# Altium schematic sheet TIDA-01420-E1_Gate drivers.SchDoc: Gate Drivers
size 431 x 279 mm; Date: Not shown in title block; ApprovedBy: Not shown in title block; CheckedBy: Not shown in title block; Author: Not shown in title block; CompanyName: Not shown in title block; DrawnBy: PN; Engineer: PN; Organization: Not shown in title block; Address1: Not shown in title block; Address2: Not shown in title block; Address3: Not shown in title block; Address4: Not shown in title block; DocumentNumber: 1; Revision: Use project parameter SCH_Rev; SheetNumber: 2; SheetTotal: 5; PageSetup: Record=PageOptions¦CenterHorizontal=True¦CenterVertical=True¦PrintScale=1.00¦XCorrection=1.00¦YCorrection=1.00¦PrintKind=0¦BorderSize=5000000¦LeftOffset=0¦BottomOffset=0¦Orientation=2¦PaperLength=1000¦PaperWidth=1000¦Scale=100¦PaperSource=15¦PrintQuality=600¦MediaType=1¦DitherType=10¦PaperKind=Letter¦PrintScaleMode=1
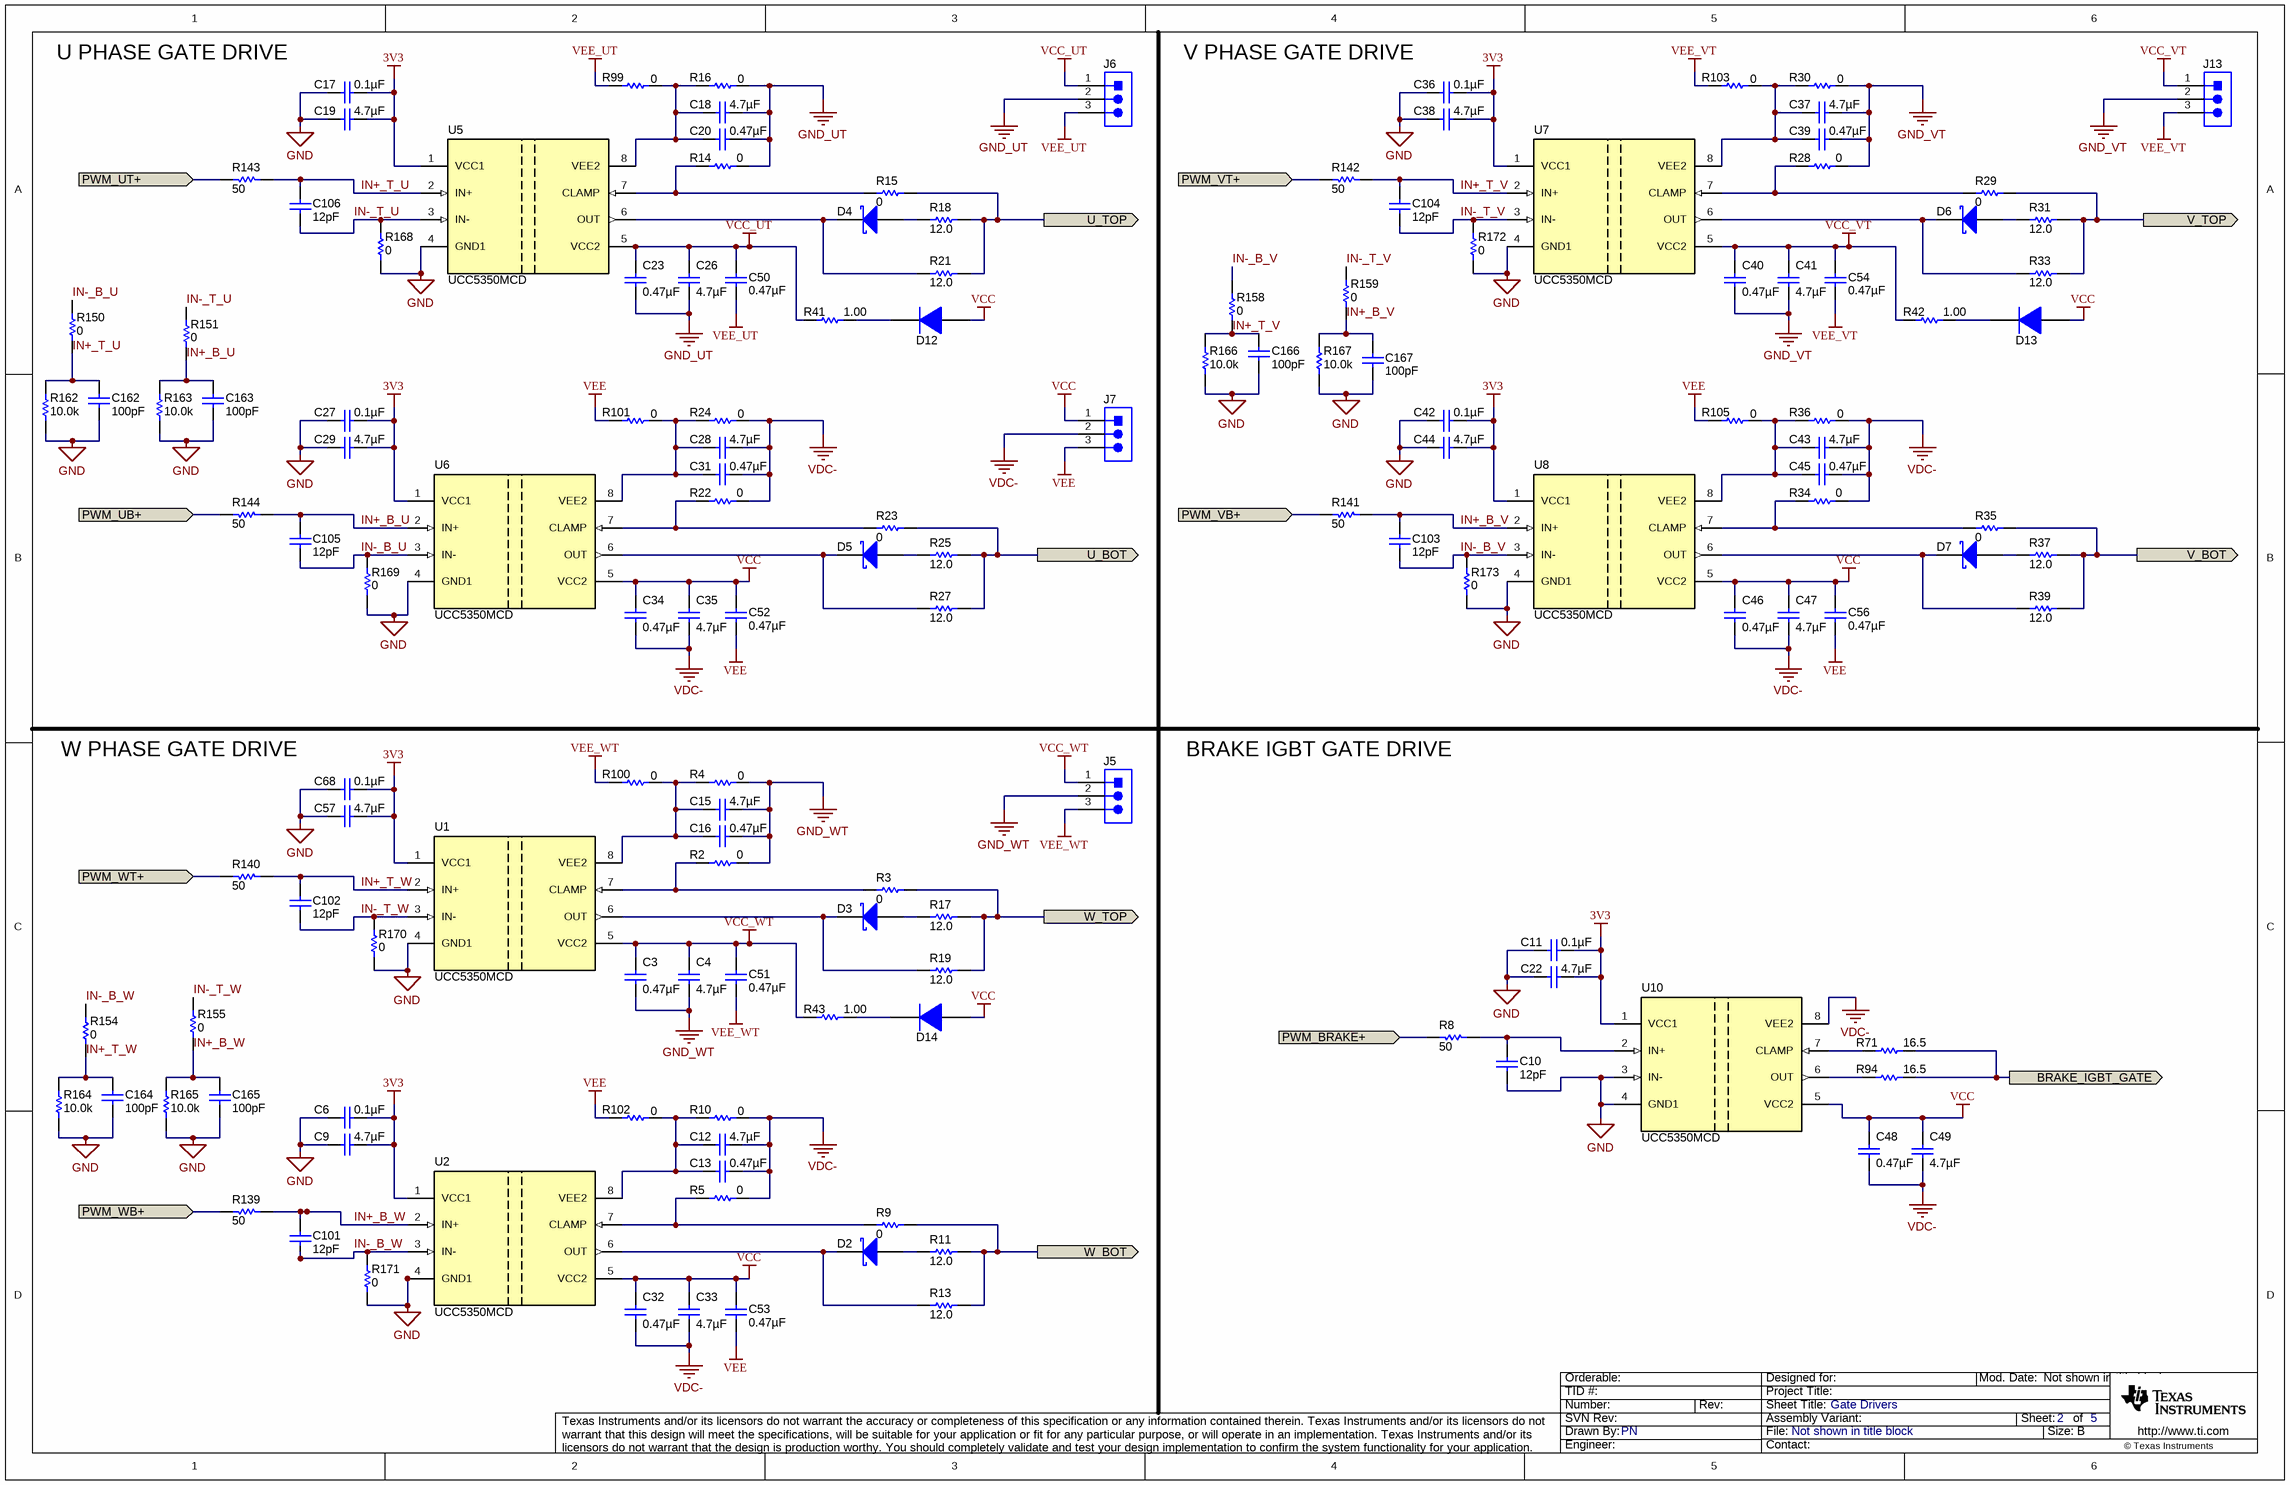
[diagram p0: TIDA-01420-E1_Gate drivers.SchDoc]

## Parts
C3  ValueDisplayed: 0.47µF  [0603]  (hidden comment: C1608X7R1H474K080AC)
C4  ValueDisplayed: 4.7µF  [0805_HV]  (hidden comment: C2012X7R1V475K125AC)
C6  ValueDisplayed: 0.1µF  [0603]  (hidden comment: C1608X7R1H104K)
C9  ValueDisplayed: 4.7µF  [0805_HV]  (hidden comment: C2012X7R1V475K125AC)
C10  ValueDisplayed: 12pF  [0603]  (hidden comment: GRM1885C1H120JA01D)
C11  ValueDisplayed: 0.1µF  [0603]  (hidden comment: C1608X7R1H104K)
C12  ValueDisplayed: 4.7µF  [0805_HV]  (hidden comment: C2012X7R1V475K125AC)
C13  ValueDisplayed: 0.47µF  [0603]  (hidden comment: C1608X7R1H474K080AC)
C15  ValueDisplayed: 4.7µF  [0805_HV]  (hidden comment: C2012X7R1V475K125AC)
C16  ValueDisplayed: 0.47µF  [0603]  (hidden comment: C1608X7R1H474K080AC)
C17  ValueDisplayed: 0.1µF  [0603]  (hidden comment: C1608X7R1H104K)
C18  ValueDisplayed: 4.7µF  [0805_HV]  (hidden comment: C2012X7R1V475K125AC)
C19  ValueDisplayed: 4.7µF  [0805_HV]  (hidden comment: C2012X7R1V475K125AC)
C20  ValueDisplayed: 0.47µF  [0603]  (hidden comment: C1608X7R1H474K080AC)
C22  ValueDisplayed: 4.7µF  [0805_HV]  (hidden comment: C2012X7R1V475K125AC)
C23  ValueDisplayed: 0.47µF  [0603]  (hidden comment: C1608X7R1H474K080AC)
C26  ValueDisplayed: 4.7µF  [0805_HV]  (hidden comment: C2012X7R1V475K125AC)
C27  ValueDisplayed: 0.1µF  [0603]  (hidden comment: C1608X7R1H104K)
C28  ValueDisplayed: 4.7µF  [0805_HV]  (hidden comment: C2012X7R1V475K125AC)
C29  ValueDisplayed: 4.7µF  [0805_HV]  (hidden comment: C2012X7R1V475K125AC)
C31  ValueDisplayed: 0.47µF  [0603]  (hidden comment: C1608X7R1H474K080AC)
C32  ValueDisplayed: 0.47µF  [0603]  (hidden comment: C1608X7R1H474K080AC)
C33  ValueDisplayed: 4.7µF  [0805_HV]  (hidden comment: C2012X7R1V475K125AC)
C34  ValueDisplayed: 0.47µF  [0603]  (hidden comment: C1608X7R1H474K080AC)
C35  ValueDisplayed: 4.7µF  [0805_HV]  (hidden comment: C2012X7R1V475K125AC)
C36  ValueDisplayed: 0.1µF  [0603]  (hidden comment: C1608X7R1H104K)
C37  ValueDisplayed: 4.7µF  [0805_HV]  (hidden comment: C2012X7R1V475K125AC)
C38  ValueDisplayed: 4.7µF  [0805_HV]  (hidden comment: C2012X7R1V475K125AC)
C39  ValueDisplayed: 0.47µF  [0603]  (hidden comment: C1608X7R1H474K080AC)
C40  ValueDisplayed: 0.47µF  [0603]  (hidden comment: C1608X7R1H474K080AC)
C41  ValueDisplayed: 4.7µF  [0805_HV]  (hidden comment: C2012X7R1V475K125AC)
C42  ValueDisplayed: 0.1µF  [0603]  (hidden comment: C1608X7R1H104K)
C43  ValueDisplayed: 4.7µF  [0805_HV]  (hidden comment: C2012X7R1V475K125AC)
C44  ValueDisplayed: 4.7µF  [0805_HV]  (hidden comment: C2012X7R1V475K125AC)
C45  ValueDisplayed: 0.47µF  [0603]  (hidden comment: C1608X7R1H474K080AC)
C46  ValueDisplayed: 0.47µF  [0603]  (hidden comment: C1608X7R1H474K080AC)
C47  ValueDisplayed: 4.7µF  [0805_HV]  (hidden comment: C2012X7R1V475K125AC)
C48  ValueDisplayed: 0.47µF  [0603]  (hidden comment: C1608X7R1H474K080AC)
C49  ValueDisplayed: 4.7µF  [0805_HV]  (hidden comment: C2012X7R1V475K125AC)
C50  ValueDisplayed: 0.47µF  [0603]  (hidden comment: C1608X7R1H474K080AC)
C51  ValueDisplayed: 0.47µF  [0603]  (hidden comment: C1608X7R1H474K080AC)
C52  ValueDisplayed: 0.47µF  [0603]  (hidden comment: C1608X7R1H474K080AC)
C53  ValueDisplayed: 0.47µF  [0603]  (hidden comment: C1608X7R1H474K080AC)
C54  ValueDisplayed: 0.47µF  [0603]  (hidden comment: C1608X7R1H474K080AC)
C56  ValueDisplayed: 0.47µF  [0603]  (hidden comment: C1608X7R1H474K080AC)
C57  ValueDisplayed: 4.7µF  [0805_HV]  (hidden comment: C2012X7R1V475K125AC)
C68  ValueDisplayed: 0.1µF  [0603]  (hidden comment: C1608X7R1H104K)
C101  ValueDisplayed: 12pF  [0603]  (hidden comment: GRM1885C1H120JA01D)
C102  ValueDisplayed: 12pF  [0603]  (hidden comment: GRM1885C1H120JA01D)
C103  ValueDisplayed: 12pF  [0603]  (hidden comment: GRM1885C1H120JA01D)
C104  ValueDisplayed: 12pF  [0603]  (hidden comment: GRM1885C1H120JA01D)
C105  ValueDisplayed: 12pF  [0603]  (hidden comment: GRM1885C1H120JA01D)
C106  ValueDisplayed: 12pF  [0603]  (hidden comment: GRM1885C1H120JA01D)
C162  ValueDisplayed: 100pF  [0603]  (hidden comment: CGA3E2NP01H101J080AA)
C163  ValueDisplayed: 100pF  [0603]  (hidden comment: CGA3E2NP01H101J080AA)
C164  ValueDisplayed: 100pF  [0603]  (hidden comment: CGA3E2NP01H101J080AA)
C165  ValueDisplayed: 100pF  [0603]  (hidden comment: CGA3E2NP01H101J080AA)
C166  ValueDisplayed: 100pF  [0603]  (hidden comment: CGA3E2NP01H101J080AA)
C167  ValueDisplayed: 100pF  [0603]  (hidden comment: CGA3E2NP01H101J080AA)
D2  MSS2P3-M3/89A  [MicroSMP]  (value not drawn)
D3  MSS2P3-M3/89A  [MicroSMP]  (value not drawn)
D4  MSS2P3-M3/89A  [MicroSMP]  (value not drawn)
D5  MSS2P3-M3/89A  [MicroSMP]  (value not drawn)
D6  MSS2P3-M3/89A  [MicroSMP]  (value not drawn)
D7  MSS2P3-M3/89A  [MicroSMP]  (value not drawn)
D12  BYG23T-M3/TR  [SMA]  (value not drawn)
D13  BYG23T-M3/TR  [SMA]  (value not drawn)
D14  BYG23T-M3/TR  [SMA]  (value not drawn)
J5  800-10-003-10-001000  [Mill-Max_800-10-003-10-001000]  (value not drawn)
J6  800-10-003-10-001000  [Mill-Max_800-10-003-10-001000]  (value not drawn)
J7  800-10-003-10-001000  [Mill-Max_800-10-003-10-001000]  (value not drawn)
J13  800-10-003-10-001000  [Mill-Max_800-10-003-10-001000]  (value not drawn)
R2  ValueDisplayed: 0  [0603]  (hidden comment: CRCW06030000Z0EA)
R3  ValueDisplayed: 0  [1206]  (hidden comment: CRCW12060000Z0EA)
R4  ValueDisplayed: 0  [0603]  (hidden comment: CRCW06030000Z0EA)
R5  ValueDisplayed: 0  [0603]  (hidden comment: CRCW06030000Z0EA)
R8  ValueDisplayed: 50  [0603]  (hidden comment: CRCW06031K00FKEA)
R9  ValueDisplayed: 0  [1206]  (hidden comment: CRCW12060000Z0EA)
R10  ValueDisplayed: 0  [0603]  (hidden comment: CRCW06030000Z0EA)
R11  ValueDisplayed: 12.0  [1206]  (hidden comment: RC1206FR-0712RL)
R13  ValueDisplayed: 12.0  [1206]  (hidden comment: RC1206FR-0712RL)
R14  ValueDisplayed: 0  [0603]  (hidden comment: CRCW06030000Z0EA)
R15  ValueDisplayed: 0  [1206]  (hidden comment: CRCW12060000Z0EA)
R16  ValueDisplayed: 0  [0603]  (hidden comment: CRCW06030000Z0EA)
R17  ValueDisplayed: 12.0  [1206]  (hidden comment: RC1206FR-0712RL)
R18  ValueDisplayed: 12.0  [1206]  (hidden comment: RC1206FR-0712RL)
R19  ValueDisplayed: 12.0  [1206]  (hidden comment: RC1206FR-0712RL)
R21  ValueDisplayed: 12.0  [1206]  (hidden comment: RC1206FR-0712RL)
R22  ValueDisplayed: 0  [0603]  (hidden comment: CRCW06030000Z0EA)
R23  ValueDisplayed: 0  [1206]  (hidden comment: CRCW12060000Z0EA)
R24  ValueDisplayed: 0  [0603]  (hidden comment: CRCW06030000Z0EA)
R25  ValueDisplayed: 12.0  [1206]  (hidden comment: RC1206FR-0712RL)
R27  ValueDisplayed: 12.0  [1206]  (hidden comment: RC1206FR-0712RL)
R28  ValueDisplayed: 0  [0603]  (hidden comment: CRCW06030000Z0EA)
R29  ValueDisplayed: 0  [1206]  (hidden comment: CRCW12060000Z0EA)
R30  ValueDisplayed: 0  [0603]  (hidden comment: CRCW06030000Z0EA)
R31  ValueDisplayed: 12.0  [1206]  (hidden comment: RC1206FR-0712RL)
R33  ValueDisplayed: 12.0  [1206]  (hidden comment: RC1206FR-0712RL)
R34  ValueDisplayed: 0  [0603]  (hidden comment: CRCW06030000Z0EA)
R35  ValueDisplayed: 0  [1206]  (hidden comment: CRCW12060000Z0EA)
R36  ValueDisplayed: 0  [0603]  (hidden comment: CRCW06030000Z0EA)
R37  ValueDisplayed: 12.0  [1206]  (hidden comment: RC1206FR-0712RL)
R39  ValueDisplayed: 12.0  [1206]  (hidden comment: RC1206FR-0712RL)
R41  ValueDisplayed: 1.00  [1206]  (hidden comment: CRCW12061R00FKEA)
R42  ValueDisplayed: 1.00  [1206]  (hidden comment: CRCW12061R00FKEA)
R43  ValueDisplayed: 1.00  [1206]  (hidden comment: CRCW12061R00FKEA)
R71  ValueDisplayed: 16.5  [1206]  (hidden comment: CRCW120616R5FKEA)
R94  ValueDisplayed: 16.5  [1206]  (hidden comment: CRCW120616R5FKEA)
R99  ValueDisplayed: 0  [0603]  (hidden comment: CRCW06030000Z0EA)
R100  ValueDisplayed: 0  [0603]  (hidden comment: CRCW06030000Z0EA)
R101  ValueDisplayed: 0  [0603]  (hidden comment: CRCW06030000Z0EA)
R102  ValueDisplayed: 0  [0603]  (hidden comment: CRCW06030000Z0EA)
R103  ValueDisplayed: 0  [0603]  (hidden comment: CRCW06030000Z0EA)
R105  ValueDisplayed: 0  [0603]  (hidden comment: CRCW06030000Z0EA)
R139  ValueDisplayed: 50  [0603]  (hidden comment: CRCW06031K00FKEA)
R140  ValueDisplayed: 50  [0603]  (hidden comment: CRCW06031K00FKEA)
R141  ValueDisplayed: 50  [0603]  (hidden comment: CRCW06031K00FKEA)
R142  ValueDisplayed: 50  [0603]  (hidden comment: CRCW06031K00FKEA)
R143  ValueDisplayed: 50  [0603]  (hidden comment: CRCW06031K00FKEA)
R144  ValueDisplayed: 50  [0603]  (hidden comment: CRCW06031K00FKEA)
R150  ValueDisplayed: 0  [0603]  (hidden comment: ERJ-3GEY0R00V)
R151  ValueDisplayed: 0  [0603]  (hidden comment: ERJ-3GEY0R00V)
R154  ValueDisplayed: 0  [0603]  (hidden comment: ERJ-3GEY0R00V)
R155  ValueDisplayed: 0  [0603]  (hidden comment: ERJ-3GEY0R00V)
R158  ValueDisplayed: 0  [0603]  (hidden comment: ERJ-3GEY0R00V)
R159  ValueDisplayed: 0  [0603]  (hidden comment: ERJ-3GEY0R00V)
R162  ValueDisplayed: 10.0k  [0603]  (hidden comment: ERJ-3EKF1002V)
R163  ValueDisplayed: 10.0k  [0603]  (hidden comment: ERJ-3EKF1002V)
R164  ValueDisplayed: 10.0k  [0603]  (hidden comment: ERJ-3EKF1002V)
R165  ValueDisplayed: 10.0k  [0603]  (hidden comment: ERJ-3EKF1002V)
R166  ValueDisplayed: 10.0k  [0603]  (hidden comment: ERJ-3EKF1002V)
R167  ValueDisplayed: 10.0k  [0603]  (hidden comment: ERJ-3EKF1002V)
R168  ValueDisplayed: 0  [0603]  (hidden comment: ERJ-3GEY0R00V)
R169  ValueDisplayed: 0  [0603]  (hidden comment: ERJ-3GEY0R00V)
R170  ValueDisplayed: 0  [0603]  (hidden comment: ERJ-3GEY0R00V)
R171  ValueDisplayed: 0  [0603]  (hidden comment: ERJ-3GEY0R00V)
R172  ValueDisplayed: 0  [0603]  (hidden comment: ERJ-3GEY0R00V)
R173  ValueDisplayed: 0  [0603]  (hidden comment: ERJ-3GEY0R00V)
U1  UCC5350MCD  [D0008B_HV]
U2  UCC5350MCD  [D0008B_HV]
U5  UCC5350MCD  [D0008B_HV]
U6  UCC5350MCD  [D0008B_HV]
U7  UCC5350MCD  [D0008B_HV]
U8  UCC5350MCD  [D0008B_HV]
U10  UCC5350MCD  [D0008B_HV]

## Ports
BRAKE_IGBT_GATE (out), PWM_BRAKE+ (in), PWM_UB+ (in), PWM_UT+ (in), PWM_VB+ (in), PWM_VT+ (in), PWM_WB+ (in), PWM_WT+ (in), U_BOT (out), U_TOP (out), V_BOT (out), V_TOP (out), W_BOT (out), W_TOP (out)

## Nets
3V3: C6.1 C9.1 C11.1 C17.1 C19.1 C22.1 C27.1 C29.1 C36.1 C38.1 C42.1 C44.1 C57.1 C68.1 U1.1(VCC1) U2.1(VCC1) U5.1(VCC1) U6.1(VCC1) U7.1(VCC1) U8.1(VCC1) U10.1(VCC1)
GND: C6.2 C9.2 C10.2 C11.2 C17.2 C19.2 C22.2 C27.2 C29.2 C36.2 C38.2 C42.2 C44.2 C57.2 C68.2 C162.2 C163.2 C164.2 C165.2 C166.2 C167.2 R162.1 R163.1 R164.1 R165.1 R166.1 R167.1 R168.1 R169.1 R170.1 R171.1 R172.1 R173.1 U1.4(GND1) U2.4(GND1) U5.4(GND1) U6.4(GND1) U7.4(GND1) U8.4(GND1) U10.3(IN-) U10.4(GND1)
GND_UT: C18.1 C20.1 C23.2 C26.2 J6.2 R14.2 R16.2
GND_VT: C37.1 C39.1 C40.2 C41.2 J13.2 R28.2 R30.2
GND_WT: C3.2 C4.2 C15.1 C16.1 J5.2 R2.2 R4.2
VCC: C32.1 C33.1 C34.1 C35.1 C46.1 C47.1 C48.1 C49.1 C52.1 C53.1 C56.1 D12.2(A) D13.2(A) D14.2(A) J7.1 U2.5(VCC2) U6.5(VCC2) U8.5(VCC2) U10.5(VCC2)
VCC_UT: C23.1 C26.1 C50.1 J6.1 R41.1 U5.5(VCC2)
VCC_VT: C40.1 C41.1 C54.1 J13.1 R42.1 U7.5(VCC2)
VCC_WT: C3.1 C4.1 C51.1 J5.1 R43.1 U1.5(VCC2)
VDC-: C12.1 C13.1 C28.1 C31.1 C32.2 C33.2 C34.2 C35.2 C43.1 C45.1 C46.2 C47.2 C48.2 C49.2 J7.2 R5.2 R10.2 R22.2 R24.2 R34.2 R36.2 U10.8(VEE2)
VEE: C52.2 C53.2 C56.2 J7.3 R101.1 R102.1 R105.1
VEE_UT: C50.2 J6.3 R99.1
VEE_VT: C54.2 J13.3 R103.1
VEE_WT: C51.2 J5.3 R100.1
BRAKE_IGBT_GATE: R71.2 R94.2 ; port BRAKE_IGBT_GATE
IN+_B_U: C105.1 C163.1 R144.1 R151.1 R163.2 U6.2(IN+)
IN+_B_V: C103.1 C167.1 R141.1 R159.1 R167.2 U8.2(IN+)
IN+_B_W: C101.1 C165.1 R139.1 R155.1 R165.2 U2.2(IN+)
IN+_T_U: C106.1 C162.1 R143.1 R150.2 R162.2 U5.2(IN+)
IN+_T_V: C104.1 C166.1 R142.1 R158.1 R166.2 U7.2(IN+)
IN+_T_W: C102.1 C164.1 R140.1 R154.1 R164.2 U1.2(IN+)
IN-_B_U: C105.2 R150.1 R169.2 U6.3(IN-)
IN-_B_V: C103.2 R158.2 R173.2 U8.3(IN-)
IN-_B_W: C101.2 R154.2 R171.2 U2.3(IN-)
IN-_T_U: C106.2 R151.2 R168.2 U5.3(IN-)
IN-_T_V: C104.2 R159.2 R172.2 U7.3(IN-)
IN-_T_W: C102.2 R155.2 R170.2 U1.3(IN-)
PWM_BRAKE+: R8.2 ; port PWM_BRAKE+
PWM_UB+: R144.2 ; port PWM_UB+
PWM_UT+: R143.2 ; port PWM_UT+
PWM_VB+: R141.2 ; port PWM_VB+
PWM_VT+: R142.2 ; port PWM_VT+
PWM_WB+: R139.2 ; port PWM_WB+
PWM_WT+: R140.2 ; port PWM_WT+
U_BOT: R23.2 R25.2 R27.2 ; port U_BOT
U_TOP: R15.2 R18.2 R21.2 ; port U_TOP
V_BOT: R35.2 R37.2 R39.2 ; port V_BOT
V_TOP: R29.2 R31.2 R33.2 ; port V_TOP
W_BOT: R9.2 R11.2 R13.2 ; port W_BOT
W_TOP: R3.2 R17.2 R19.2 ; port W_TOP
NetC10_1: C10.1 R8.1 U10.2(IN+)
NetC12_2: C12.2 C13.2 R10.1 R102.2 U2.8(VEE2)
NetC15_2: C15.2 C16.2 R4.1 R100.2 U1.8(VEE2)
NetC18_2: C18.2 C20.2 R16.1 R99.2 U5.8(VEE2)
NetC28_2: C28.2 C31.2 R24.1 R101.2 U6.8(VEE2)
NetC37_2: C37.2 C39.2 R30.1 R103.2 U7.8(VEE2)
NetC43_2: C43.2 C45.2 R36.1 R105.2 U8.8(VEE2)
NetD2_1: D2.1(K) R13.1 U2.6(OUT)
NetD2_2: D2.2(A) R11.1
NetD3_1: D3.1(K) R19.1 U1.6(OUT)
NetD3_2: D3.2(A) R17.1
NetD4_1: D4.1(K) R21.1 U5.6(OUT)
NetD4_2: D4.2(A) R18.1
NetD5_1: D5.1(K) R27.1 U6.6(OUT)
NetD5_2: D5.2(A) R25.1
NetD6_1: D6.1(K) R33.1 U7.6(OUT)
NetD6_2: D6.2(A) R31.1
NetD7_1: D7.1(K) R39.1 U8.6(OUT)
NetD7_2: D7.2(A) R37.1
NetD12_1: D12.1(K) R41.2
NetD13_1: D13.1(K) R42.2
NetD14_1: D14.1(K) R43.2
NetR2_1: R2.1 R3.1 U1.7(CLAMP)
NetR5_1: R5.1 R9.1 U2.7(CLAMP)
NetR14_1: R14.1 R15.1 U5.7(CLAMP)
NetR22_1: R22.1 R23.1 U6.7(CLAMP)
NetR28_1: R28.1 R29.1 U7.7(CLAMP)
NetR34_1: R34.1 R35.1 U8.7(CLAMP)
NetR71_1: R71.1 U10.7(CLAMP)
NetR94_1: R94.1 U10.6(OUT)

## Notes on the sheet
- U PHASE GATE DRIVE
- V PHASE GATE DRIVE
- W PHASE GATE DRIVE
- BRAKE IGBT GATE DRIVE

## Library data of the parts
C3 C13 C16 C20 C23 C31 C32 C34 C39 C40 C45 C46 C48 C50-C54 C56 = C1608X7R1H474K080AC: CAP, CERM, 0.47 µF, 50 V, +/- 10%, X7R, 0603; Manufacturer: TDK; Polarized: N; CompType: Capacitor; Value: 0.47uF; U/M: EA; Cap_F: 0.00000047; Tolerance_%: 10; ESR_ohm: 0.010974; Value1: 0.010974 ohm; VDC_V: 50; Value2: 50V; IRMS_A: 1.57483; TaMin_C: -55; TaMax_C: 125; SizeArea_mm2: 1.28; SizeAreaWB_mm2: 4.68; SizeX_mm: 1.6; SizeY_mm: 0.8; SizeZ_mm: 1; AEC Category: Q200
C4 C9 C12 C15 C18 C19 C22 C26 C28 C29 C33 C35 C37 C38 C41 C43 C44 C47 C49 C57 = C2012X7R1V475K125AC: CAP, CERM, 4.7 µF, 35 V, +/- 10%, X7R, 0805; Manufacturer: TDK; Polarized: N; CompType: Capacitor; Value: 4.7uF; U/M: EA; Cap_F: 0.0000047; Tolerance_%: 10; ESR_ohm: 0.002346; Value1: 0.002346 ohm; VDC_V: 35; Value2: 35V; IRMS_A: 4.26021; TaMin_C: -55; TaMax_C: 125; Cap_Case: 0805; SizeArea_mm2: 2.5; SizeAreaWB_mm2: 6.75; SizeX_mm: 2; SizeY_mm: 1.25; SizeZ_mm: 1.45; AEC Category: Q200
C6 C11 C17 C27 C36 C42 C68 = C1608X7R1H104K: CAP, CERM, 0.1 µF, 50 V, +/- 10%, X7R, 0603; Manufacturer: TDK; Polarized: N; CompType: Capacitor; Value: 0.1uF; U/M: EA; Cap_F: 0.0000001; Tolerance_%: 10; ESR_ohm: 0.017; Value1: 0.017 ohm; VDC_V: 50; Value2: 50V; TaMin_C: -55; TaMax_C: 125; AEC Category: Q200
C10 C101-C106 = GRM1885C1H120JA01D: CAP, CERM, 12 pF, 50 V, +/- 5%, C0G/NP0, 0603; Manufacturer: MuRata; Polarized: N; CompType: Capacitor; Value: 12pF; U/M: EA; Cap_F: 0.000000000012; Tolerance_%: 5; Value1: Unknown; VDC_V: 50; Value2: 50V; TaMin_C: -55; TaMax_C: 125; AEC Category: Q200; SizeArea_mm2: 1.28; SizeAreaWB_mm2: 4.68; SizeX_mm: 1.6; SizeY_mm: 0.8; SizeZ_mm: 1
C162-C167 = CGA3E2NP01H101J080AA: CAP, CERM, 100 pF, 50 V,+/- 5%, C0G/NP0, AEC-Q200 Grade 0, 0603; Manufacturer: TDK; Polarized: N; CompType: Capacitor; Value: 100pF; U/M: EA; Cap_F: 0.0000000001; Tolerance_%: 5; Value1: Unknown; VDC_V: 50; Value2: 50V; TaMin_C: -55; TaMax_C: 150; AEC Category: Q200; AEC Qualified: Y; AEC Grade: 0; SizeArea_mm2: 1.28; SizeAreaWB_mm2: 4.68; SizeX_mm: 1.6; SizeY_mm: 0.8; SizeZ_mm: 1; Green_Lifecycle: Active; Green_REACh: Passed
D2-D7 = MSS1P3L-M3/89A: Diode, Schottky, 30 V, 2 A, AEC-Q101, MicroSMP; Manufacturer: Vishay-Semiconductor; U/M: EA; Vf_V: 0.6; Value: 30V; Value1: 2A; Value2: 0.6V; Io_A: 1; Vr_V: 30; TJmax_C: 150; RJC_CperW: 40; AEC Category: Q101; AEC Qualified: Y
D12-D14 = BYG23T-M3/TR: Diode, Ultrafast, 1300 V, 1 A, SMA; Manufacturer: Vishay-Semiconductor; U/M: EA; Vf_V: 1.9; Value: 1300V; Value1: 1A; Value2: 1.9V; Io_A: 1; Vr_V: 1300; TJmax_C: 150; AEC Category: Q101; AEC Qualified: N
J5-J7 J13 = 800-10-003-10-001000: Header, 100mil, 3x1, TH; Manufacturer: Mill-Max; SymbolCreator: a0799628
R2 R4 R5 R10 R14 R16 R22 R24 R28 R30 R34 R36 R99-R103 R105 = CRCW06030000Z0EA: RES, 0, 5%, 0.1 W, 0603; Manufacturer: Vishay-Dale; CompType: Resistor; Value: 0; Value_Code: 0000; Tolerance_%: 5; Power_W: 0.1; Value2: 0.1W; VDC_V: 75; TempCo: 200 ppm/C; EIA_Code: E24; U/M: EA; AEC Category: Q200; SizeArea_mm2: 1.28; SizeX_mm: 1.6; SizeY_mm: 0.8; SizeZ_mm: 1
R3 R9 R15 R23 R29 R35 = CRCW12060000Z0EA: RES, 0, 5%, 0.25 W, 1206; Manufacturer: Vishay-Dale; CompType: Resistor; Value: 0; Value_Code: 0000; Tolerance_%: 5; Power_W: 0.25; Value2: 0.25W; VDC_V: 200; TempCo: 200 ppm/C; EIA_Code: E24; U/M: EA; AEC Category: Q200; SizeArea_mm2: 5.12; SizeX_mm: 3.2; SizeY_mm: 1.6; SizeZ_mm: 1.35
R8 R139-R144 = CRCW06031K00FKEA: RES, 50, 1%, 0.1 W, 0603; Manufacturer: Vishay-Dale; CompType: Resistor; Value: 1.00k; Res_ohm: 1000; Value_Code: 1k00; Tolerance_%: 1; Power_W: 0.1; Value2: 0.1W; VDC_V: 75; TempCo: 100 ppm/C; EIA_Code: E96; U/M: EA; AEC Category: Q200; SizeArea_mm2: 1.28; SizeX_mm: 1.6; SizeY_mm: 0.8
R11 R13 R17-R19 R21 R25 R27 R31 R33 R37 R39 = RC1206FR-0712RL: RES, 12.0, 1%, 0.25 W, 1206; Manufacturer: Yageo America; CompType: Resistor; Value: 12.0; Res_ohm: 12; Value_Code: 12R0; Tolerance_%: 1; Power_W: 0.25; Value2: 0.25W; VDC_V: 200; TempCo: 100 ppm/C; U/M: EA; AEC Category: Q200; SizeArea_mm2: 5.12; SizeX_mm: 3.2; SizeY_mm: 1.6; SizeZ_mm: 1.35
R41-R43 = CRCW12061R00FKEA: RES, 1.00, 1%, 0.25 W, 1206; Manufacturer: Vishay-Dale; CompType: Resistor; Value: 1.00; Res_ohm: 1; Value_Code: 1R00; Power_W: 0.25; Value2: 0.25W; VDC_V: 200; TempCo: 100 ppm/C; SizeArea_mm2: 5.12; SizeX_mm: 3.2; SizeY_mm: 1.6; SizeZ_mm: 1.35; EIA_Code: E96; U/M: EA; AEC Category: Q200
R71 R94 = CRCW120616R5FKEA: RES, 16.5, 1%, 0.25 W, 1206; Manufacturer: Vishay-Dale; CompType: Resistor; Value: 16.5; Value_Code: 16R5; Tolerance_%: 1; Power_W: 0.25; Value2: 0.25W; VDC_V: 200; TempCo: 100 ppm/C; EIA_Code: E96; U/M: EA; AEC Category: Q200; SizeArea_mm2: 5.12; SizeX_mm: 3.2; SizeY_mm: 1.6; SizeZ_mm: 1.35
R150 R151 R154 R155 R158 R159 R168-R173 = ERJ-3GEY0R00V: RES, 0, 5%, 0.1 W, 0603; Manufacturer: Panasonic; CompType: Resistor; Value: 0; Value_Code: 0000; Tolerance_%: 5; Power_W: 0.1; Value2: 0.1W; VDC_V: 50; TempCo: 600 ppm/C; EIA_Code: E24; U/M: EA; AEC Category: Q200; SizeArea_mm2: 1.28; SizeX_mm: 1.6; SizeY_mm: 0.8; SizeZ_mm: 1; Green_Lifecycle: Active; Green_REACh: Passed
R162-R167 = ERJ-3EKF1002V: RES, 10.0 k, 1%, 0.1 W, 0603; Manufacturer: Panasonic; CompType: Resistor; Value: 10.0k; Res_ohm: 10000; Value_Code: 10k0; Tolerance_%: 1; Power_W: 0.1; Value2: 0.1W; VDC_V: 75; TempCo: 100 ppm/C; EIA_Code: E96; U/M: EA; AEC Category: Q200; SizeArea_mm2: 1.28; SizeX_mm: 1.6; SizeY_mm: 0.8; Green_Lifecycle: Active; Green_REACh: Passed
U1 U2 U5-U8 U10 = UCC5350MCD: Isolated Gate Drivers With High CMTI and Scalable Drive Strength, D0008B (SOIC-8); Manufacturer: Texas Instruments; SymbolCreator: Altium; SizeArea_mm2: 29.4; SizeAreaWB_mm2: 55.2; SizeX_mm: 6; SizeY_mm: 4.9; SizeZ_mm: 1.75; CompType: IC; U/M: EA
